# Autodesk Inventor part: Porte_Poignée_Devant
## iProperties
Created: 2009-01
Part Number: Porte_Poignée_Devant
Document SubType Name: Modeling
Designer: claivier
Norme de conversion: STEP AP214IS
Nom du fichier: SW3dPS-P1-30-101-11_P1_LIFT.STEP
Préprocesseur: SolidWorks 2008
Postprocesseur: Build: 344a, Release: 11 SP2 - Date: Fri 08/18/2006
Unités envoyées: MILLIMETERS
Incertitude: 1e-05
Author: claivier
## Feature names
1. Base1
